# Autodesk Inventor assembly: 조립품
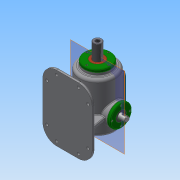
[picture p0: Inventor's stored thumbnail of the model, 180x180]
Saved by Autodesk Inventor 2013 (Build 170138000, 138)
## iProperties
Created: 2019-10
Part Number: 조립품
Document SubType Name: Assembly
Designer: Administrator
Author: Administrator
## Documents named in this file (17)
- C:\Users\Administrator\Desktop\뜸부기\391004V1039\조립품.iam
- C:\Users\Administrator\Desktop\뜸부기\391004V1039\본체.ipt
- C:\Users\Administrator\Desktop\뜸부기\391004V1039\가변스프링.ipt
- C:\Users\Administrator\Desktop\뜸부기\391004V1039\개스킷 A.ipt
- C:\Users\Administrator\Desktop\뜸부기\391004V1039\개스킷 B.ipt
- C:\Users\Administrator\Desktop\뜸부기\391004V1039\고정플레이트.ipt
- C:\Users\Administrator\Desktop\뜸부기\391004V1039\베어링 6205.ipt
- 베어링 6205.ipt
- C:\Users\Administrator\Desktop\뜸부기\391004V1039\볼트 M4x0.7.ipt
- C:\Users\Administrator\Desktop\뜸부기\391004V1039\부시.ipt
- C:\Users\Administrator\Desktop\뜸부기\391004V1039\상부커버.ipt
- C:\Users\Administrator\Desktop\뜸부기\391004V1039\슬라이드 커버.ipt
- C:\Users\Administrator\Desktop\뜸부기\391004V1039\슬라이드.ipt
- C:\Users\Administrator\Desktop\뜸부기\391004V1039\오일 실 25 38 8.ipt
- C:\Users\Administrator\Desktop\뜸부기\391004V1039\육각머리볼트 M4.ipt
- C:\Users\Administrator\Desktop\뜸부기\391004V1039\축 커버.ipt
- C:\Users\Administrator\Desktop\뜸부기\391004V1039\편심축.ipt
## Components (17 placed, 5 different names)
1. 개스킷 A:1
2. 개스킷 B:1
3. 고정플레이트:1 — 플러쉬:57
4. 개스킷 B:2
5. 가변스프링:1
6. M4x0.7:1
7. M4x0.7:4
8. M4x0.7:5
9. M4x0.7:6
10. M4x0.7:2
11. M4x0.7:7
12. M4x0.7:8
13. M4x0.7:9
14. M4x0.7:3
15. M4x0.7:10
16. M4x0.7:11
17. M4x0.7:12
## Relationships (1: Flush 1)
- 플러쉬:57 [Flush]: 고정플레이트:1
